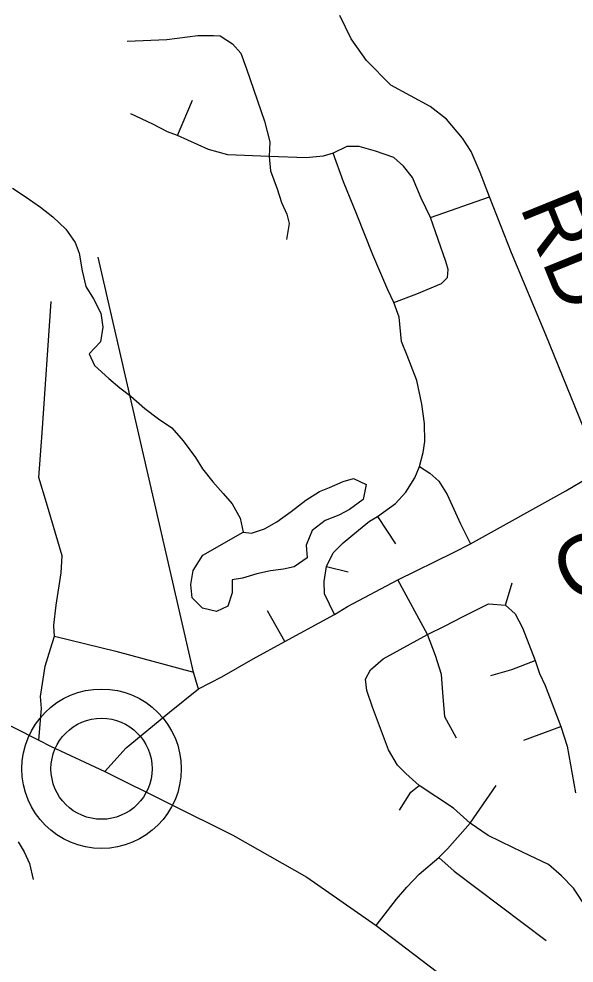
# Model space of a CAD drawing. Extents: x 0 to 34, y 0 to 22.
# Drawn here: x 7.1532 to 7.4123, y 16.551 to 16.9915 of the extents above; entities that cross this region are included whole.
import ezdxf

# ---------------------------------------------------------------- set-up
doc = ezdxf.new("R2010")
doc.units = 0
for name, color, linetype in [('GM_X_County_Road', 7, 'Continuous'), ('GM_X_County_Road_Text', 7, 'Continuous'), ('GM_X_Minor_Lake', 7, 'Continuous'), ('GM_X_Minor_River', 7, 'Continuous'), ('GM_X_Township_Road', 7, 'Continuous'), ('GM_X_Township_Road_Text', 7, 'Continuous'), ('GM_X_Unincorporated', 7, 'Continuous'), ('GM_X_Unincorporated_Location', 7, 'Continuous')]:
    doc.layers.add(name, color=color, linetype=linetype)

msp = doc.modelspace()

# ---------------------------------------------------------------- linework, layer by layer
at = {"layer": 'GM_X_County_Road'}
for points in [[(7.19333, 16.64041), (7.20332, 16.65151), (7.22346, 16.66802), (7.23706, 16.67889), (7.24789, 16.68454), (7.26258, 16.6929), (7.27732, 16.70097), (7.30041, 16.7137), (7.30657, 16.71733), (7.32996, 16.72984), (7.35593, 16.74253), (7.36398, 16.74664), (7.40847, 16.77128), (7.42472, 16.78096)], [(6.98231, 16.74868), (6.99034, 16.74677), (6.99916, 16.74579), (7.01386, 16.74302), (7.0235, 16.73877), (7.03087, 16.73436), (7.0437, 16.72538), (7.05881, 16.71456), (7.0736, 16.70297), (7.10612, 16.68418), (7.11515, 16.67897), (7.16247, 16.65497), (7.16793, 16.65218), (7.19333, 16.64041), (7.25308, 16.61077), (7.28754, 16.59115), (7.31986, 16.56856), (7.37981, 16.52304), (7.40908, 16.50276), (7.41634, 16.49781), (7.42771, 16.4889), (7.43497, 16.4833), (7.45283, 16.47096)]]:
    msp.add_lwpolyline(points, dxfattribs=at)
at = {"layer": 'GM_X_Minor_Lake'}
msp.add_line((7.23909, 16.74126), (7.25791, 16.75209), dxfattribs=at)
msp.add_lwpolyline([(7.25791, 16.75209), (7.2617, 16.75164), (7.26782, 16.75361), (7.27358, 16.75691), (7.28032, 16.76172), (7.28707, 16.7669), (7.29342, 16.77096), (7.2982, 16.77295), (7.30452, 16.77568), (7.3093, 16.7771), (7.31532, 16.77432), (7.31385, 16.76732), (7.30749, 16.76269), (7.3025, 16.75994), (7.29618, 16.75741), (7.29002, 16.75278), (7.28722, 16.74599), (7.28767, 16.74009), (7.2817, 16.73584), (7.27675, 16.7348), (7.27065, 16.73397), (7.26417, 16.73258), (7.25748, 16.73063), (7.25272, 16.72977), (7.25279, 16.72369), (7.25077, 16.71746), (7.2454, 16.71509), (7.23897, 16.71655), (7.23413, 16.7214), (7.2335, 16.72769), (7.23458, 16.73413), (7.23909, 16.74126)], dxfattribs=at)
at = {"layer": 'GM_X_Minor_River'}
for points in [[(7.15022, 16.91258), (7.15622, 16.90866), (7.16333, 16.90358), (7.16913, 16.89909), (7.17509, 16.89346), (7.17952, 16.8871), (7.18132, 16.88212), (7.18268, 16.87392), (7.18443, 16.86666), (7.18811, 16.86088), (7.1914, 16.85417), (7.19241, 16.84768), (7.19132, 16.84086), (7.18608, 16.83527), (7.18844, 16.82971), (7.19516, 16.82368), (7.20039, 16.81939), (7.20544, 16.81549), (7.21197, 16.80966), (7.21833, 16.80497), (7.22451, 16.80066), (7.2299, 16.79466), (7.23563, 16.78694), (7.23894, 16.78156), (7.24376, 16.77557), (7.24859, 16.77015), (7.25267, 16.76531), (7.25652, 16.75858), (7.25791, 16.75209)], [(7.15287, 16.60766), (7.15563, 16.60286), (7.15818, 16.59749), (7.15993, 16.59004)]]:
    msp.add_lwpolyline(points, dxfattribs=at)
at = {"layer": 'GM_X_Township_Road'}
for p, q in [((7.22719, 16.93701), (7.23428, 16.95355)), ((7.34533, 16.89879), (7.37286, 16.90843)), ((7.32054, 16.75937), (7.32899, 16.74666)), ((7.29681, 16.73601), (7.30686, 16.73351)), ((7.3803, 16.71805), (7.38344, 16.72844)), ((7.27732, 16.70097), (7.26926, 16.71538)), ((7.38888, 16.65505), (7.40603, 16.66132))]:
    msp.add_line(p, q, dxfattribs=at)
for points in [[(7.42472, 16.78096), (7.39902, 16.84412), (7.38312, 16.88239), (7.37286, 16.90843), (7.36837, 16.91984), (7.36421, 16.92964), (7.36018, 16.93586), (7.35269, 16.94474), (7.34508, 16.95062), (7.32678, 16.96055), (7.31534, 16.97199), (7.3082, 16.9821), (7.30299, 16.99313)], [(7.20373, 16.98111), (7.22224, 16.98192), (7.23677, 16.98377), (7.24405, 16.9838), (7.24706, 16.98351), (7.25293, 16.97991), (7.25685, 16.97548), (7.25947, 16.96823), (7.26782, 16.94378), (7.27033, 16.93413), (7.26993, 16.92723), (7.27064, 16.92065), (7.27376, 16.91219), (7.27577, 16.90586), (7.27828, 16.90032), (7.27925, 16.89597), (7.27805, 16.8886)], [(7.32809, 16.85918), (7.33895, 16.86324), (7.34366, 16.8653), (7.35046, 16.86799), (7.35315, 16.87076), (7.35347, 16.87464), (7.35244, 16.87827), (7.34533, 16.89879), (7.34095, 16.9078), (7.33682, 16.91756), (7.33269, 16.92281), (7.32818, 16.92676), (7.31955, 16.92976), (7.31204, 16.93201), (7.30622, 16.93201), (7.29989, 16.92884), (7.29513, 16.92737), (7.28726, 16.92665), (7.26993, 16.92723), (7.25072, 16.92811), (7.24164, 16.93056), (7.22719, 16.93701), (7.22264, 16.93876), (7.2157, 16.94237), (7.20545, 16.94721)], [(7.30041, 16.7137), (7.29584, 16.72326), (7.29569, 16.72908), (7.29681, 16.73601), (7.29987, 16.74241), (7.30454, 16.74709), (7.31161, 16.75294), (7.31686, 16.75714), (7.32054, 16.75937), (7.32899, 16.76541), (7.33372, 16.77074), (7.33794, 16.77738), (7.34006, 16.78261), (7.34187, 16.78915), (7.34257, 16.79438), (7.34247, 16.80273), (7.34116, 16.81168), (7.33895, 16.82285), (7.33432, 16.83452), (7.3318, 16.84103), (7.3307, 16.85233), (7.32809, 16.85918), (7.32531, 16.86507), (7.31835, 16.88136), (7.31092, 16.90018), (7.3046, 16.91552), (7.29989, 16.92884)], [(7.23706, 16.67889), (7.23605, 16.68192), (7.23462, 16.68672), (7.19017, 16.88038)], [(7.16957, 16.70869), (7.17064, 16.71806), (7.17301, 16.73304), (7.17338, 16.74099), (7.1661, 16.76572), (7.16251, 16.77748), (7.16414, 16.79839), (7.16826, 16.85964)], [(7.34006, 16.78261), (7.34488, 16.77957), (7.3491, 16.77581), (7.35305, 16.7696), (7.3592, 16.7559), (7.36398, 16.74664)], [(7.35738, 16.65588), (7.35194, 16.66594), (7.35095, 16.67731), (7.35045, 16.68572), (7.34765, 16.69446), (7.34386, 16.70436), (7.32996, 16.72984)], [(7.41805, 16.57686), (7.41196, 16.58595), (7.40636, 16.59173), (7.40026, 16.597), (7.39152, 16.60129), (7.3836, 16.60492), (7.37222, 16.61053), (7.36381, 16.6163), (7.35606, 16.62322), (7.3399, 16.63394), (7.3338, 16.63939), (7.32984, 16.64334), (7.32572, 16.65043), (7.31813, 16.67039), (7.31549, 16.67814), (7.315, 16.68342), (7.31731, 16.68787), (7.32324, 16.69298), (7.34386, 16.70436), (7.3521, 16.70832), (7.36018, 16.7126), (7.37239, 16.71854), (7.3803, 16.71805), (7.38475, 16.71392), (7.38822, 16.70749), (7.39416, 16.69215), (7.39613, 16.68605), (7.39877, 16.68045), (7.40603, 16.66132), (7.409, 16.65225), (7.41296, 16.63048)], [(7.16247, 16.65497), (7.16381, 16.66973), (7.16324, 16.67544), (7.1655, 16.68956), (7.16797, 16.69761), (7.16977, 16.70358), (7.16952, 16.7082), (7.16957, 16.70869)], [(7.16977, 16.70358), (7.19848, 16.69658), (7.23462, 16.68672)], [(7.37344, 16.68513), (7.38327, 16.68803), (7.39416, 16.69215)], [(7.31986, 16.56856), (7.32947, 16.5809), (7.33421, 16.58637), (7.33998, 16.59247), (7.34922, 16.60022), (7.35318, 16.60434), (7.36381, 16.6163), (7.37585, 16.63394)], [(7.33083, 16.6224), (7.33611, 16.63081), (7.3399, 16.63394)], [(7.34922, 16.60022), (7.35631, 16.59395), (7.39927, 16.56155)]]:
    msp.add_lwpolyline(points, dxfattribs=at)
at = {"layer": 'GM_X_Unincorporated'}
for radius in [0.0372, 0.02358]:
    msp.add_circle((7.19179, 16.64168), radius, dxfattribs=at)
at = {"layer": 'GM_X_Unincorporated_Location'}
msp.add_line((7.19179, 16.64168), (7.19179, 16.64168), dxfattribs=at)

# ---------------------------------------------------------------- texts
at = {"layer": 'GM_X_County_Road_Text'}
msp.add_text('C-123', height=0.028409, rotation=28.9506, dxfattribs=at).set_placement((7.41254, 16.71738))
at = {"layer": 'GM_X_Township_Road_Text'}
msp.add_text('RD', height=0.028409, rotation=292.0722, dxfattribs=at).set_placement((7.38678, 16.90383))

doc.saveas('drawing.dxf')
